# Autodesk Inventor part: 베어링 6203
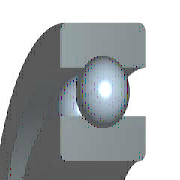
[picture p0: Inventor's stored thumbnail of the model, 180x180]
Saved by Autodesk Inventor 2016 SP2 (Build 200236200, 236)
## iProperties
IsCustomPart: 0
Created: 2016-04
Part Number: 베어링 6203
Material: 강철, 연강
Description: 깊은 그루브 볼 베어링
Document SubType Name: Modeling
Standard: KS B 2023
Designer: mdu
Standards Organization: KS
Language: ko-KR
Size Designation: 6203 - 17 x 40 x 12
Categories: <MemberInstance><Categories><Category DisplayName="샤프트 부품" InternalName="7f7aeb1f-a693-4053-b835-cee3144e0d98" Mnemonic="SHFT"><Category DisplayName="베어링" Inter
Density: 7.86 g/cm^3
Mass: 64.9809 g
Surface Area: 64.3582 cm^2
Volume: 8.26729 cm^3
Appearance: 노란색
Author: mdu
Revision Number: 1
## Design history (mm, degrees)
sketch "스케치" dims "d0" = 5.98 (= -0.26 x WD + 0.26 x BD)
  geometry: L1 (3.01, 14.25)-(8.99, 14.25); L2 (6, 14.25)-(6, 11.26); L3 (6, 14.25)-(6, 17.24); L4 (3.778, 12.249)-(0, 12.249); L5 (0, 8.5)-(12, 8.5); L6 (3.778, 16.251)-(0, 16.251); L7 (0, 20)-(12, 20); L8 (12, 8.5)-(12, 12.249); L9 (8.222, 12.249)-(12, 12.249); L10 (8.222, 16.251)-(12, 16.251); L11 (12, 20)-(12, 16.251); L12 (-1.4, 0)-(8.4, 0) reference; L13 (0, -0.3)-(0, 5.3) reference
  constraints: 22 end point, 4 point on line, 2 collinear, 2 perpendicular, 2 symmetric about line, 1 midpoint, 1 parallel, 14 other
  dimensions: "d9" = 17 diameter of L5 L12 (= WD); "d11" = 40 diameter of L7 L12 (= BD); "d12" = 12 distance between parallel lines of L8 L13 (= KB); "d13" = 24.498 diameter of L9 L12 (= 0.326 x BD + 0.674 x WD)
revolve "본체" stored, may be unused: angle "d6" = 90 deg
revolve "볼" stored, may be unused: angle "d7" = 90 deg
pattern_circular "IDS_ARRAYBALL[SIMPL:T]" dims angle "d3" = 360 deg
body "Solid1"
fillet "모깎기1" dims "d1" = 0.6 (= KRS)
other parameters: "WD" = 17 [user parameter; used in 5 equation terms], "BD" = 40 [user parameter; used in 5 equation terms], "KB" = 12 [user parameter; used in 1 equation term], "KRS" = 0.6 [user parameter; used in 1 equation term], "d4" = 0, "d5" = 0, "d8" = 0, "d14" = 0, "d15" = 0, "BBA" = 0 [user parameter], "BC0" = 4750000 [user parameter], "BC" = 9560000 [user parameter], "WR" = 8.5 (= 0.5 x WD) [user parameter]
